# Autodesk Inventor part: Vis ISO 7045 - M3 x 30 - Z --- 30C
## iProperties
Created: 2011-01
Part Number: Vis ISO 7045 - M3 x 30 - Z --- 30C
Document SubType Name: Modeling
Designer: eric
Density: 1 g/cm^3
Mass: 0.257006 g
Surface Area: 3.70471 cm^2
Volume: 0.257006 cm^3
Author: eric
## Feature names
1. Base1
